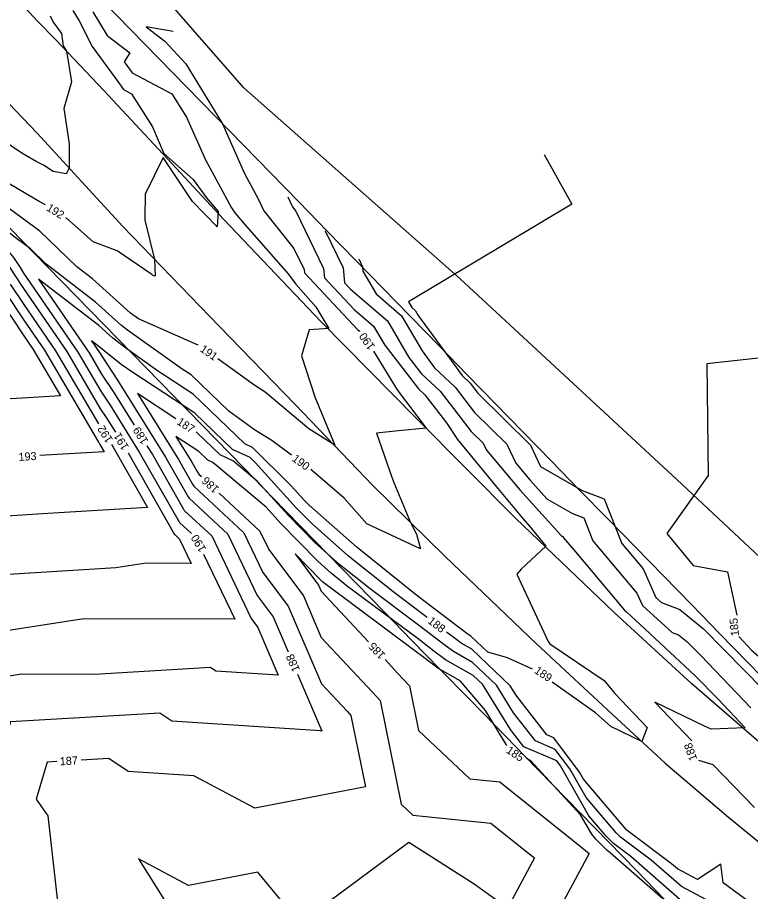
# Model space of a CAD drawing. Extents: x 2086416 to 2115205, y 575507 to 632762.
# Drawn here: x 2110278.4 to 2110459.9, y 581864.8 to 582081.1 of the extents above; entities that cross this region are included whole.
import ezdxf

# ---------------------------------------------------------------- set-up
doc = ezdxf.new("R2010")
doc.units = 0
for name, color, linetype in [('DTM Contours Major', 7, 'Continuous'), ('DTM Contours Major Text', 7, 'Continuous'), ('DTM Contours Minor', 7, 'Continuous'), ('DTM Contours Minor Text', 7, 'Continuous'), ('Exist Hydrographic FEMA Cross Section', 7, 'Continuous'), ('Exist Roads EOP', 7, 'Continuous'), ('Exist Vegetation Woods Line', 7, 'Continuous')]:
    doc.layers.add(name, color=color, linetype=linetype)

msp = doc.modelspace()

# ---------------------------------------------------------------- linework, layer by layer
at = {"layer": 'DTM Contours Major'}
for points in [[(2110316.89, 582077.63), (2110310.21, 582078.77), (2110314.85, 582075.2), (2110320.04, 582069.66), (2110329.12, 582054.79), (2110334.54, 582042.53), (2110337.96, 582036.21), (2110339.37, 582033.23), (2110346.83, 582023.95), (2110349.35, 582018.71), (2110349.43, 582017.88), (2110362.56, 582003.85), (2110363.03, 582003.44), (2110363.07, 582003.38)], [(2110265.4, 582035.83), (2110277.36, 582021.68), (2110279.01, 582019.19), (2110279.89, 582017.86), (2110293.32, 581998.29), (2110298.98, 581988.65), (2110301.29, 581985.18), (2110308.53, 581973.54), (2110318.39, 581956.29), (2110318.49, 581956.12), (2110321.45, 581953.37)], [(2110346.2, 581972.79), (2110341.33, 581976.42), (2110337.08, 581979.04), (2110330.74, 581983.65), (2110321.37, 581992.65), (2110319.17, 581994.09), (2110305.61, 582003.68), (2110304.12, 582004.86), (2110297.71, 582010.63), (2110285.4, 582020.11), (2110281.57, 582023.82), (2110277.77, 582026.61), (2110267.71, 582034.46)], [(2110366.53, 581998.49), (2110372.41, 581988.98), (2110379.53, 581979.5), (2110372.67, 581978.77), (2110367.29, 581978.19), (2110371.09, 581967.34), (2110371.56, 581965.98), (2110375.71, 581956.12), (2110377.13, 581953.24), (2110378.15, 581949.58), (2110364.85, 581955.76), (2110359.29, 581962.12), (2110351.01, 581969.2)], [(2110473.79, 581998.1), (2110449.06, 581995.35), (2110449.38, 581967.78), (2110439.16, 581953.41), (2110445.67, 581945.45), (2110454.14, 581943.92), (2110456.52, 581933.16)], [(2110324.46, 581948.27), (2110332.16, 581932.18), (2110294.81, 581932.29), (2110269.72, 581928.4), (2110263.82, 581928.04), (2110261.87, 581927.92), (2110261.42, 581927.97), (2110260.59, 581928.07), (2110255.91, 581922.27), (2110255.52, 581921), (2110255.06, 581919.59)], [(2110399.57, 581900.92), (2110394.25, 581909.56), (2110387.99, 581916.96), (2110382.41, 581920.1), (2110378.62, 581922.94), (2110377.05, 581924.14), (2110354.52, 581940.97), (2110353.93, 581941.45), (2110353.44, 581941.88), (2110347.12, 581948.36), (2110352.92, 581940.64), (2110353.57, 581939.12), (2110365.28, 581926.58)], [(2110457, 581927.88), (2110460.22, 581924.41), (2110465.69, 581919.7), (2110467.09, 581918.26), (2110471.2, 581912.48), (2110474.08, 581909.72), (2110478.74, 581904.23), (2110484.88, 581896.98), (2110489.67, 581891.41), (2110497.24, 581885.1), (2110503.54, 581879.8), (2110508.99, 581875.69), (2110517.48, 581867.91), (2110520.9, 581865), (2110528.46, 581858.48)], [(2110369.37, 581922.2), (2110372.5, 581918.84), (2110375.41, 581915.72), (2110377.65, 581904.64), (2110390.4, 581892.7), (2110397.79, 581891.94), (2110416.83, 581876.68), (2110419.88, 581874.24), (2110407.25, 581850.79)], [(2110477.66, 581830.47), (2110467.52, 581837.44), (2110466.26, 581838.39), (2110465.28, 581839.19), (2110446.86, 581855.82), (2110445.45, 581856.9), (2110444.68, 581857.31), (2110425.22, 581874.31), (2110424.26, 581875.03), (2110421.59, 581877.72), (2110420.54, 581878.96), (2110417.81, 581883.75), (2110405.43, 581897.24), (2110404.4, 581897.68)]]:
    msp.add_lwpolyline(points, dxfattribs=at)
at = {"layer": 'DTM Contours Minor'}
for points in [[(2110239.63, 582076.69), (2110234.85, 582080.48), (2110227.63, 582086.48), (2110212.34, 582095.86), (2110223.97, 582080.06), (2110225.38, 582078.5), (2110237.38, 582062.8), (2110241.12, 582057.39), (2110253.02, 582043.75), (2110256.71, 582037.96), (2110256.86, 582037.78), (2110266.82, 582025.99), (2110275.38, 582013.07), (2110279.92, 582006.23), (2110285.03, 581998.78), (2110298.39, 581976.04), (2110298.49, 581975.89), (2110298.8, 581975.39), (2110299.81, 581973.62), (2110296.89, 581973.45), (2110283.89, 581972.66)], [(2110292.08, 582082.87), (2110293.64, 582080.28), (2110296.88, 582073.9), (2110303.18, 582065.27), (2110304.59, 582063.3), (2110306.62, 582062.23), (2110311.76, 582054.07), (2110314.61, 582047.48), (2110321.83, 582041.03), (2110325.2, 582036.5), (2110328.05, 582033.12), (2110327.81, 582029.25), (2110321.69, 582035.56), (2110314.41, 582046.42), (2110309.98, 582037.35), (2110309.94, 582031.5), (2110309.89, 582030.94), (2110312.31, 582021.21), (2110312.43, 582017.13), (2110312.3, 582017.07), (2110311.76, 582017.34), (2110311.65, 582017.5), (2110303.02, 582023.39), (2110297.14, 582025.56), (2110290.52, 582031.45), (2110290.36, 582031.55)], [(2110297.06, 582082.5), (2110300.58, 582076.68), (2110306.18, 582072.38), (2110304.81, 582070.11), (2110306.76, 582067.39), (2110316.62, 582062.17), (2110320.22, 582056.47), (2110324.91, 582045.84), (2110331.33, 582033.98), (2110332.3, 582032.66), (2110334.52, 582030.03), (2110345.38, 582017.66), (2110347.26, 582015.14), (2110352.23, 582009.51), (2110355.48, 582004.16), (2110350.59, 582003.84), (2110348.66, 581997.34), (2110351.99, 581987.24), (2110356.93, 581975.27), (2110350.5, 581979.3), (2110339.72, 581988.41), (2110337.16, 581989.99), (2110335.08, 581991.5), (2110327.98, 581996.6)], [(2110286.44, 582081.48), (2110287.22, 582079.93), (2110289.28, 582077.11), (2110289.71, 582074.07), (2110290.54, 582072.75), (2110291.77, 582065.16), (2110289.82, 582058.59), (2110291.13, 582049.84), (2110291.2, 582043.81), (2110290.42, 582042.42), (2110287.21, 582043.02), (2110284.81, 582044.52), (2110282.98, 582045.45), (2110279.43, 582047.55), (2110274.33, 582051.01), (2110267.62, 582055.41), (2110261.78, 582062.06), (2110255.13, 582066.52), (2110245.2, 582072.27), (2110244.33, 582072.96)], [(2110323.07, 582000.02), (2110308.3, 582006.54), (2110306.38, 582007.9), (2110306.25, 582008), (2110296.94, 582016.39), (2110293.07, 582019.36), (2110283.91, 582028.25), (2110274.82, 582034.9), (2110263.82, 582043.5), (2110263.61, 582043.67), (2110259.77, 582048.03), (2110243.43, 582058.99), (2110257.37, 582043), (2110258.38, 582041.42), (2110258.61, 582041.15), (2110273.85, 582023.12), (2110277.8, 582017.15), (2110279.9, 582013.99), (2110290.56, 581998.46), (2110298.79, 581984.45), (2110300.36, 581982.08), (2110302.61, 581978.47)], [(2110408.74, 582047.16), (2110415.62, 582034.86), (2110375.19, 582010.71), (2110376.01, 582009.3), (2110376.89, 582008.54), (2110377.61, 582007.32), (2110388.47, 581992.46), (2110390.48, 581990.58), (2110392.38, 581988.12), (2110405.41, 581975.28), (2110407.87, 581969.97), (2110410, 581968.7), (2110418.21, 581964.01), (2110423.65, 581961.96), (2110428, 581950.92), (2110433.28, 581944.67), (2110436.4, 581937.56), (2110437.8, 581936.3), (2110442.36, 581934.62), (2110448.26, 581929.8), (2110458.33, 581919.57), (2110459.63, 581918.22), (2110463.77, 581913.99)], [(2110285.28, 582034.73), (2110285.17, 582034.79), (2110283.74, 582035.52), (2110276.51, 582039.81)], [(2110255.45, 582036.89), (2110255.87, 582036.23), (2110255.98, 582036.1), (2110263.31, 582027.43), (2110274.17, 582011.04), (2110279.93, 582002.35), (2110282.27, 581998.95), (2110289.03, 581987.44), (2110276.79, 581986.7), (2110269.64, 581987.54), (2110256.43, 581989.07), (2110188.99, 581905.51)], [(2110345.27, 582036.72), (2110346.44, 582034.26), (2110347.29, 582033.2), (2110354.16, 582018.94), (2110354.38, 582016.68), (2110361.69, 582008.85), (2110366.5, 582004.71), (2110369.3, 581999.97), (2110377.63, 581989.21), (2110379.25, 581987.7), (2110384.62, 581980.75), (2110387.34, 581976.65), (2110397.29, 581964.54), (2110401.81, 581959.08), (2110402.88, 581957.8), (2110405.13, 581955.2), (2110409.18, 581950.28), (2110403.07, 581944.54), (2110402.04, 581943.3), (2110409.75, 581926.69), (2110410.17, 581926.05), (2110423.62, 581917), (2110426.24, 581913.8), (2110434.29, 581905.41), (2110432.98, 581901.95), (2110425.3, 581905.63), (2110421.47, 581908.98), (2110410.78, 581916.6)], [(2110354.56, 582028.31), (2110358.97, 582019.17), (2110359.33, 582015.47), (2110360.83, 582013.86), (2110369.96, 582005.99), (2110375.29, 581996.97), (2110378.43, 581992.92), (2110382.99, 581988.66), (2110390.74, 581978.63), (2110393.67, 581975.74), (2110394.48, 581974), (2110402.75, 581964.19), (2110412.98, 581952.89), (2110413.32, 581952.69), (2110413.47, 581952.63), (2110413.6, 581952.32), (2110416.54, 581948.84), (2110428.57, 581934.53), (2110429.15, 581933.99), (2110433.72, 581929.77), (2110446.15, 581918.14), (2110451.84, 581912.43), (2110458.56, 581905.31), (2110450.09, 581904.97), (2110448.34, 581905.82), (2110436.15, 581911.65), (2110445.35, 581902.06)], [(2110362.85, 582021.33), (2110363.78, 582019.4), (2110363.88, 582018.32), (2110367.16, 582012.67), (2110373.42, 582007.27), (2110378.55, 581998.6), (2110381.62, 581994.4), (2110386.74, 581989.62), (2110391.56, 581983.38), (2110399.54, 581975.51), (2110401.73, 581970.79), (2110405.19, 581966.68), (2110409.47, 581961.95), (2110415.77, 581958.35), (2110418.56, 581957.29), (2110420.8, 581951.62), (2110431.76, 581938.65), (2110433.1, 581935.59), (2110440.49, 581928.93), (2110442.05, 581928.35), (2110444.08, 581926.7), (2110447.54, 581923.19), (2110459.94, 581910.24)], [(2110405.88, 581919.83), (2110399.66, 581922.63), (2110394.85, 581924.01), (2110390.64, 581928.01), (2110390.16, 581928.28), (2110389.96, 581928.43), (2110379, 581936.77), (2110376.85, 581938.38), (2110362.49, 581949.91), (2110350.59, 581960.4), (2110349.35, 581961.67), (2110346.16, 581965.18), (2110336.6, 581974.67), (2110334.68, 581975.56), (2110321.84, 581987.9), (2110313.03, 581993.67), (2110304.83, 581999.47), (2110301.99, 582001.72), (2110298.49, 582004.88), (2110283.58, 582016.35), (2110296.08, 581998.13), (2110299.18, 581992.85), (2110302.22, 581988.28), (2110307.23, 581980.22)], [(2110276.59, 582015.11), (2110279.91, 582010.11), (2110287.79, 581998.62), (2110298.43, 581980.52)], [(2110379.82, 581932.62), (2110378.51, 581933.61), (2110371.27, 581939.03), (2110360.35, 581947.8), (2110351.3, 581955.77), (2110347.4, 581959.76), (2110337.34, 581970.85), (2110335.99, 581972.19), (2110331.62, 581974.22), (2110322.31, 581983.16), (2110306.9, 581993.24), (2110304.06, 581995.25), (2110299.86, 581998.58), (2110299.26, 581999.13), (2110296.69, 582001.1), (2110298.84, 581997.97), (2110299.38, 581997.06), (2110303.15, 581991.38), (2110315.02, 581972.3), (2110320.62, 581962.5), (2110320.86, 581962.1), (2110330.44, 581953.2), (2110337.7, 581938.02), (2110341.66, 581932.76), (2110345.35, 581924.13)], [(2110317.59, 581981.81), (2110308.1, 581988.02), (2110318.26, 581971.68), (2110321.73, 581965.61), (2110322.05, 581965.09), (2110334.43, 581953.59), (2110339.15, 581943.72), (2110345.42, 581935.38), (2110353.62, 581916.19), (2110359.97, 581909.4), (2110360.94, 581908.35), (2110364.51, 581890.73), (2110337.12, 581885.39), (2110322.05, 581893.45), (2110305.74, 581894.49), (2110300.99, 581897.73), (2110294.12, 581897.32)], [(2110448.78, 581862.79), (2110442.74, 581866.02), (2110435.3, 581872.52), (2110427.65, 581878.26), (2110426.61, 581879.3), (2110419.19, 581888.04), (2110415.15, 581895.13), (2110411.53, 581899.97), (2110406.61, 581902.08), (2110401.2, 581909.01), (2110396.96, 581915.88), (2110391.03, 581921.51), (2110386.29, 581924.19), (2110384.29, 581925.69), (2110378.03, 581930.45), (2110365.69, 581939.68), (2110358.21, 581945.68), (2110352.01, 581951.14), (2110345.46, 581957.85), (2110337.74, 581966.36), (2110331.96, 581971.23), (2110331.71, 581971.4), (2110328.55, 581972.87), (2110322.79, 581978.41), (2110322.61, 581978.53)], [(2110443.71, 581861.67), (2110430.26, 581873.42), (2110425.95, 581876.64), (2110424.1, 581878.51), (2110419.86, 581883.5), (2110412.81, 581895.89), (2110411.87, 581897.15), (2110403.76, 581900.63), (2110400.42, 581904.91), (2110393.53, 581916.08), (2110391.23, 581918.26), (2110384.35, 581922.15), (2110381.46, 581924.31), (2110377.54, 581927.29), (2110360.1, 581940.32), (2110356.07, 581943.56), (2110352.73, 581946.51), (2110343.51, 581955.95), (2110339.94, 581959.88), (2110327.26, 581970.57), (2110326.71, 581970.96), (2110325.49, 581971.52), (2110323.26, 581973.67), (2110317.58, 581977.38), (2110321.51, 581971.06), (2110322.85, 581968.71), (2110323.24, 581968.08), (2110323.9, 581967.47)], [(2110301.63, 581975.45), (2110302.04, 581974.77), (2110310.59, 581959.81), (2110285.87, 581958.31), (2110269.33, 581957.31), (2110265.53, 581957.76), (2110258.51, 581958.57), (2110218.92, 581909.52), (2110215.63, 581898.75), (2110210.19, 581881.92), (2110223.48, 581854.62), (2110225.48, 581847.63), (2110225.52, 581847.51)], [(2110310.4, 581975.13), (2110311.78, 581972.92), (2110319.5, 581959.4), (2110319.67, 581959.11), (2110326.46, 581952.81), (2110336.26, 581932.33), (2110337.91, 581930.13), (2110342.94, 581918.36), (2110327.45, 581919.35), (2110326.2, 581920.21), (2110297.45, 581918.49), (2110279.39, 581918.55), (2110267.52, 581916.71), (2110261.26, 581895.57), (2110257.09, 581881.5), (2110257.62, 581880.73), (2110258.31, 581874.72), (2110261.9, 581860.82)], [(2110305.75, 581973.35), (2110317.27, 581953.18), (2110317.3, 581953.14), (2110318.49, 581952.03), (2110321.38, 581945.99), (2110310.24, 581946.03), (2110302.75, 581944.87), (2110274.84, 581943.18), (2110265.6, 581942.62), (2110263.47, 581942.87), (2110259.55, 581943.32), (2110237.41, 581915.9), (2110235.58, 581909.87), (2110226.31, 581881.2), (2110234.36, 581864.64), (2110238.85, 581848.99)], [(2110328.29, 581963.38), (2110338.41, 581953.97), (2110340.59, 581949.41), (2110349.17, 581938.01), (2110353.6, 581927.66), (2110366.24, 581914.12), (2110368.17, 581912.04), (2110373.36, 581886.45), (2110376.29, 581883.71), (2110395.58, 581881.74), (2110404.88, 581874.28), (2110406.37, 581873.09), (2110399.68, 581860.65), (2110391.46, 581866.63), (2110375.29, 581876.92), (2110353.26, 581860.55)], [(2110461.2, 581860.98), (2110453.09, 581866.98), (2110452.51, 581871.6), (2110446.72, 581867.73), (2110441.77, 581870.37), (2110440.33, 581871.63), (2110429.34, 581879.87), (2110429.12, 581880.09), (2110418.51, 581892.57), (2110417.49, 581894.37), (2110411.18, 581902.8), (2110409.45, 581903.54), (2110401.98, 581913.11), (2110400.39, 581915.69), (2110390.83, 581924.76), (2110388.22, 581926.24), (2110387.12, 581927.06), (2110384.59, 581928.99)], [(2110347.71, 581918.62), (2110353.65, 581904.72), (2110353.7, 581904.68), (2110353.7, 581904.67), (2110353.73, 581904.55), (2110353.54, 581904.51), (2110353.43, 581904.57), (2110316.59, 581906.92), (2110313.59, 581908.97), (2110276.62, 581906.77), (2110270.04, 581884.58), (2110271.75, 581882.11), (2110273.92, 581863.02), (2110279.51, 581841.39), (2110280.82, 581837.67), (2110289.39, 581831.97), (2110290.63, 581826.76), (2110299.16, 581809.22)], [(2110288.13, 581896.97), (2110285.71, 581896.82), (2110283, 581887.65), (2110285.87, 581883.5), (2110289.54, 581851.33), (2110290.58, 581847.3), (2110290.82, 581846.6), (2110292.92, 581845.21), (2110300.94, 581850.81), (2110307.98, 581835.94), (2110308.72, 581829.44), (2110328.04, 581798.41), (2110328.28, 581797.91), (2110328.33, 581797.81), (2110328.36, 581797.69), (2110328.67, 581797.32), (2110340.79, 581768.09), (2110341.88, 581750.11), (2110347.64, 581742.54), (2110348.83, 581732.84), (2110349.85, 581729.37)], [(2110447.02, 581897.33), (2110450.53, 581896.22), (2110460.85, 581885.58)], [(2110348.44, 581856.97), (2110348.37, 581856.91), (2110337.84, 581869.61), (2110320.7, 581866.27), (2110308.32, 581872.89), (2110315.01, 581862.24), (2110322.51, 581850.28), (2110327.68, 581839.37), (2110329.34, 581824.75), (2110333.87, 581817.46), (2110344.38, 581809.08), (2110345.17, 581808.24), (2110347.25, 581777.74), (2110352.06, 581766.14), (2110352.48, 581759.21), (2110359.23, 581750.34), (2110362.78, 581746.53), (2110364.99, 581737.98)]]:
    msp.add_lwpolyline(points, dxfattribs=at)
at = {"layer": 'Exist Hydrographic FEMA Cross Section'}
for points in [[(2110466.06, 581914.46), (2110459.11, 581921.57), (2110452.18, 581928.68), (2110445.24, 581935.8), (2110438.3, 581942.9), (2110431.36, 581950.02), (2110424.42, 581957.13), (2110417.48, 581964.24), (2110410.54, 581971.35), (2110403.6, 581978.47), (2110396.67, 581985.58), (2110389.73, 581992.69), (2110382.79, 581999.81), (2110375.85, 582006.91), (2110368.91, 582014.03), (2110361.97, 582021.14), (2110355.03, 582028.25), (2110348.09, 582035.36), (2110341.16, 582042.48), (2110334.22, 582049.59), (2110327.28, 582056.7), (2110320.34, 582063.82), (2110313.4, 582070.93), (2110306.46, 582078.04), (2110299.52, 582085.15)], [(2110438.57, 581862.85), (2110431.63, 581869.96), (2110424.69, 581877.07), (2110417.76, 581884.19), (2110410.82, 581891.3), (2110403.88, 581898.41), (2110396.94, 581905.52), (2110390, 581912.63), (2110383.06, 581919.75), (2110376.12, 581926.86), (2110369.18, 581933.97), (2110362.24, 581941.08), (2110355.3, 581948.2), (2110348.36, 581955.31), (2110341.43, 581962.42), (2110334.49, 581969.53), (2110327.55, 581976.64), (2110320.61, 581983.76), (2110313.67, 581990.87), (2110306.73, 581997.98), (2110299.79, 582005.09), (2110292.85, 582012.21), (2110285.92, 582019.32), (2110278.97, 582026.43), (2110272.04, 582033.54)]]:
    msp.add_lwpolyline(points, dxfattribs=at)
at = {"layer": 'Exist Roads EOP'}
for points in [[(2110283.42, 582080.08), (2110269.79, 582094.77), (2110258.57, 582106.89), (2110244.84, 582121.04), (2110232.61, 582133.97), (2110220.43, 582147.01), (2110205.56, 582162.74), (2110193.7, 582175.26), (2110182.38, 582187.32), (2110170.57, 582200.14), (2110157.55, 582213.9), (2110148.13, 582223.91), (2110139.67, 582233.18), (2110129.17, 582244.2), (2110118.25, 582256.11), (2110105.57, 582269.53), (2110093.37, 582282.59), (2110082.14, 582294.76), (2110071.88, 582305.53), (2110059.32, 582319.17)], [(2110044.03, 582306.54), (2110057.72, 582292.25), (2110067.42, 582282.08), (2110077.05, 582271.73), (2110082.67, 582265.54), (2110091.18, 582256.81), (2110101.9, 582244.92), (2110112.61, 582233.51), (2110124.83, 582220.15), (2110138.66, 582205.71), (2110150.44, 582192.87), (2110163.31, 582179.2), (2110176.51, 582165.18), (2110187.09, 582154.1), (2110200.16, 582140.29), (2110212.15, 582128.06), (2110221.2, 582117.92), (2110235.62, 582102.6), (2110247.94, 582089.65), (2110262.41, 582074.68), (2110272.71, 582063.48), (2110283.25, 582052.48)], [(2110463.15, 581900.73), (2110445.32, 581916.19), (2110426.12, 581933.84), (2110401.78, 581957.07), (2110377.09, 581981.9), (2110353.55, 582005.81), (2110329.43, 582031.08), (2110314.39, 582047.38), (2110299.73, 582063), (2110287.89, 582075.57), (2110283.42, 582080.08)], [(2110283.25, 582052.48), (2110304.42, 582029.37), (2110328.36, 582004.6), (2110347.1, 581985.36), (2110366.35, 581965.28), (2110384.3, 581947.72), (2110406.89, 581926.12), (2110426.78, 581907.62), (2110438.72, 581896.56), (2110454.4, 581883.19), (2110469.83, 581870.54)]]:
    msp.add_lwpolyline(points, dxfattribs=at)
at = {"layer": 'Exist Vegetation Woods Line'}
msp.add_lwpolyline([(2111059.79, 581657.65), (2110968.73, 581672.25), (2110864.06, 581705.25), (2110784.73, 581740.8), (2110702.3, 581784.67), (2110632.54, 581823.34), (2110568.48, 581865.95), (2110498.27, 581913.79), (2110441.66, 581966.78), (2110387.94, 582016.39), (2110334.43, 582063.69), (2110284.48, 582120.87)], dxfattribs=at)

# ---------------------------------------------------------------- texts
at = {"layer": 'DTM Contours Major Text'}
for s, rotation, p in [('190', 125.2488, (2110366.99, 581999.69)), ('190', 323.2405, (2110346.18, 581971.56)), ('190', 120.5563, (2110325.18, 581949.53)), ('185', 95.1898, (2110457.03, 581928.1)), ('185', 133.029, (2110369.61, 581923.41)), ('185', 326.1225, (2110399.2, 581899.3))]:
    msp.add_text(s, height=2, rotation=rotation, dxfattribs=at).set_placement(p)
at = {"layer": 'DTM Contours Minor Text'}
for s, rotation, p in [('192', 327.997, (2110285.36, 582033.49)), ('191', 325.112, (2110323.38, 581998.63)), ('187', 326.81, (2110317.65, 581980.58)), ('192', 122.2396, (2110302.1, 581976.6)), ('189', 121.8893, (2110310.87, 581976.27)), ('191', 121.5585, (2110306.06, 581974.79)), ('193', 3.4666, (2110278.68, 581971.34)), ('186', 137.0916, (2110328.44, 581964.61)), ('188', 322.7289, (2110379.79, 581931.39)), ('188', 113.1517, (2110348.35, 581919.68)), ('189', 326.6507, (2110406.16, 581919.02)), ('188', 109.4903, (2110446.7, 581897.58)), ('187', 3.4125, (2110288.91, 581896.01))]:
    msp.add_text(s, height=2, rotation=rotation, dxfattribs=at).set_placement(p)

doc.saveas('drawing.dxf')
